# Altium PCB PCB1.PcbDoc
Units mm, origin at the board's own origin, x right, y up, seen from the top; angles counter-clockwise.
Board outline 98 x 98 mm, 2 copper layers (Top Layer, Bottom Layer); 41 components, 34 nets, 175 pads, 20 vias.
Unrouted connection lines stored in the file: 90.
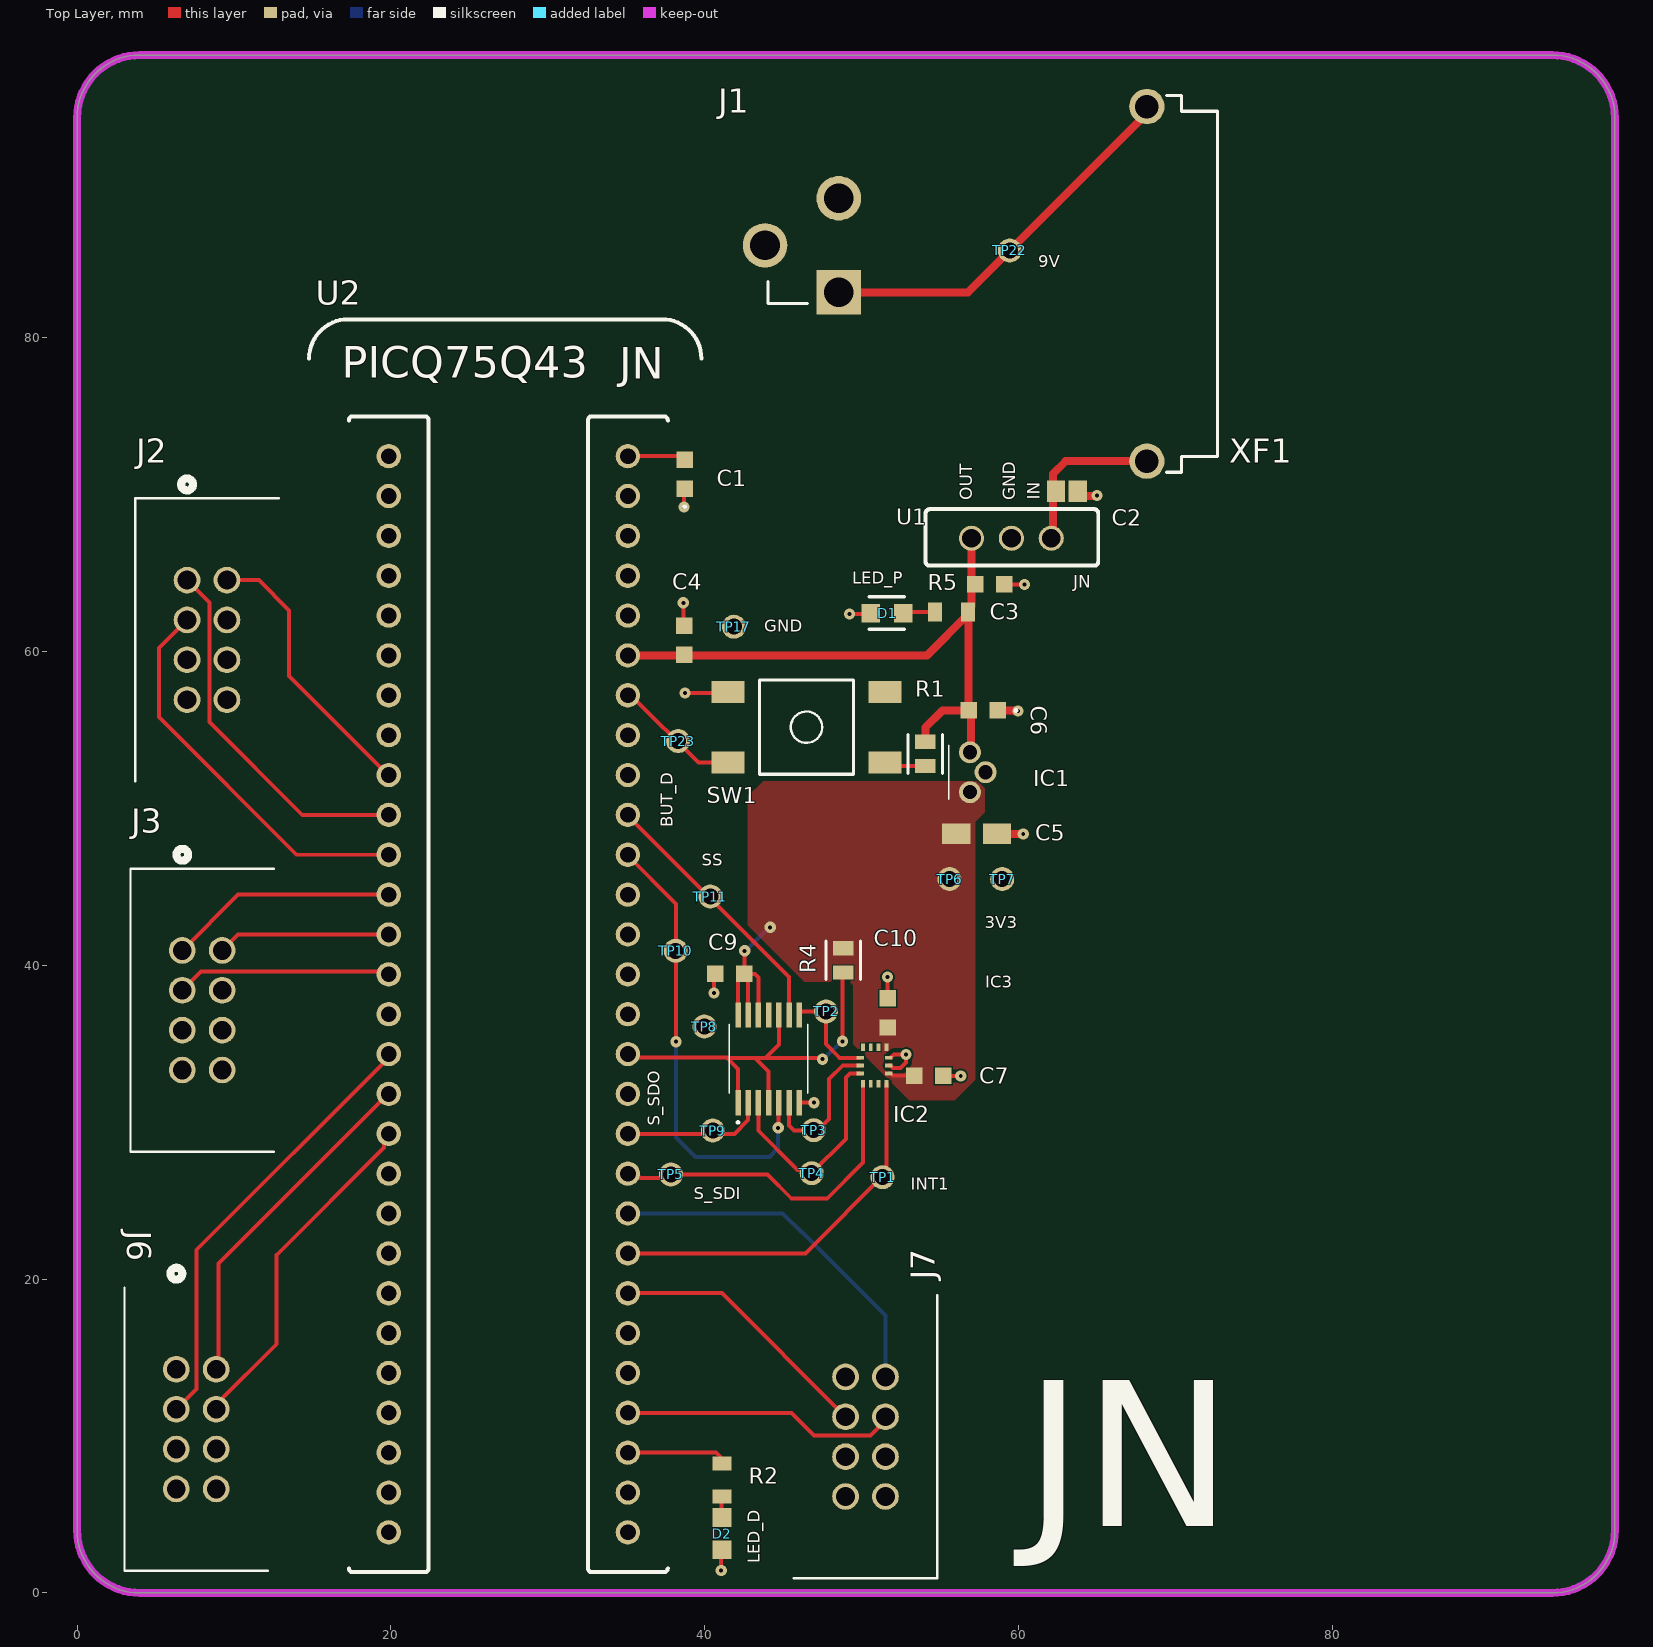
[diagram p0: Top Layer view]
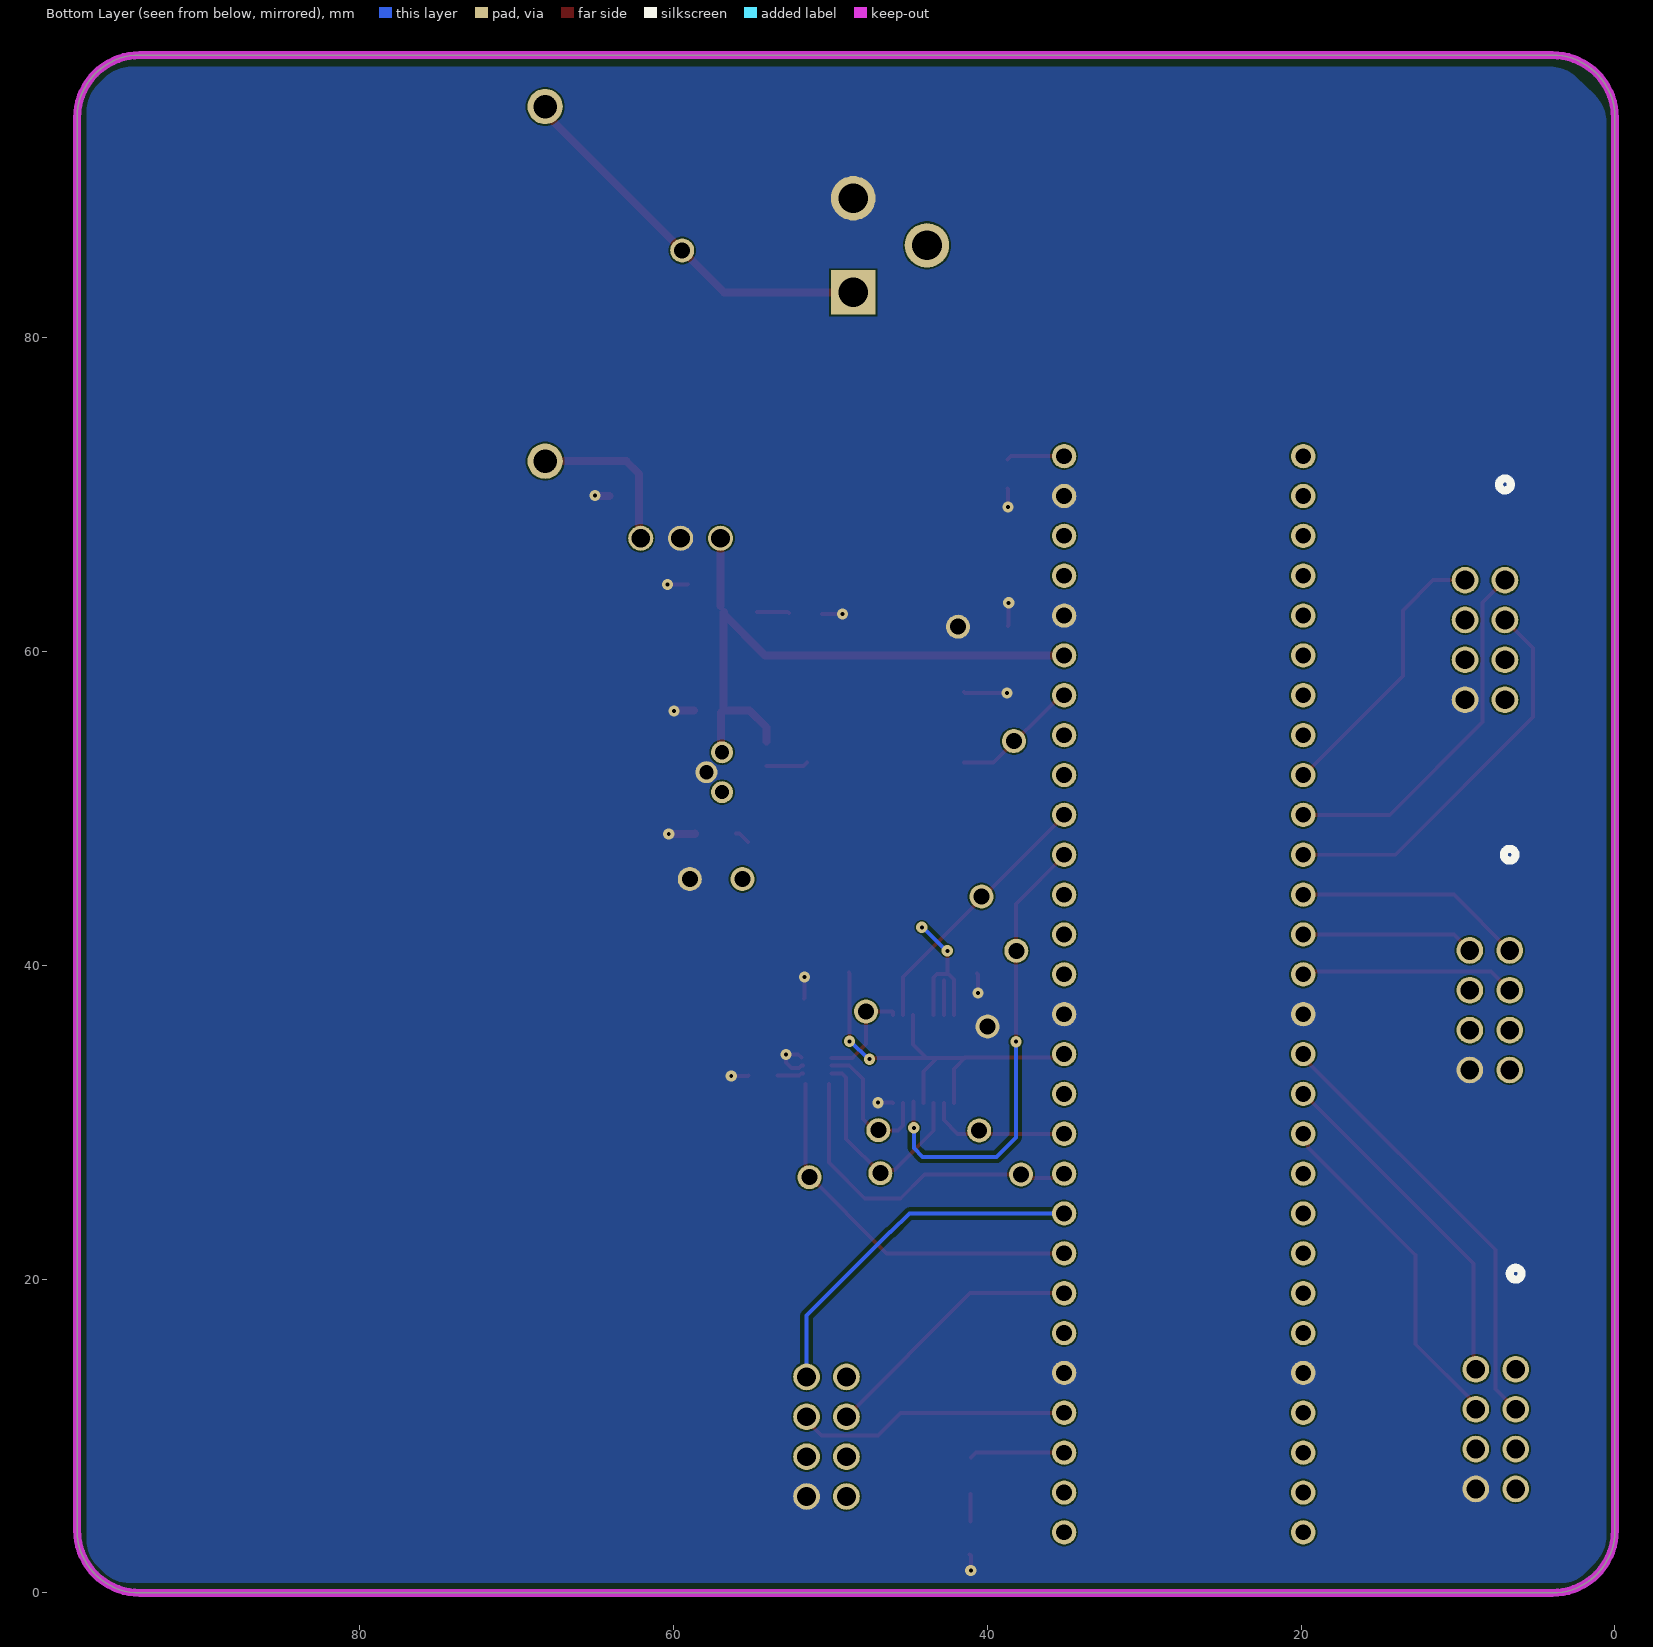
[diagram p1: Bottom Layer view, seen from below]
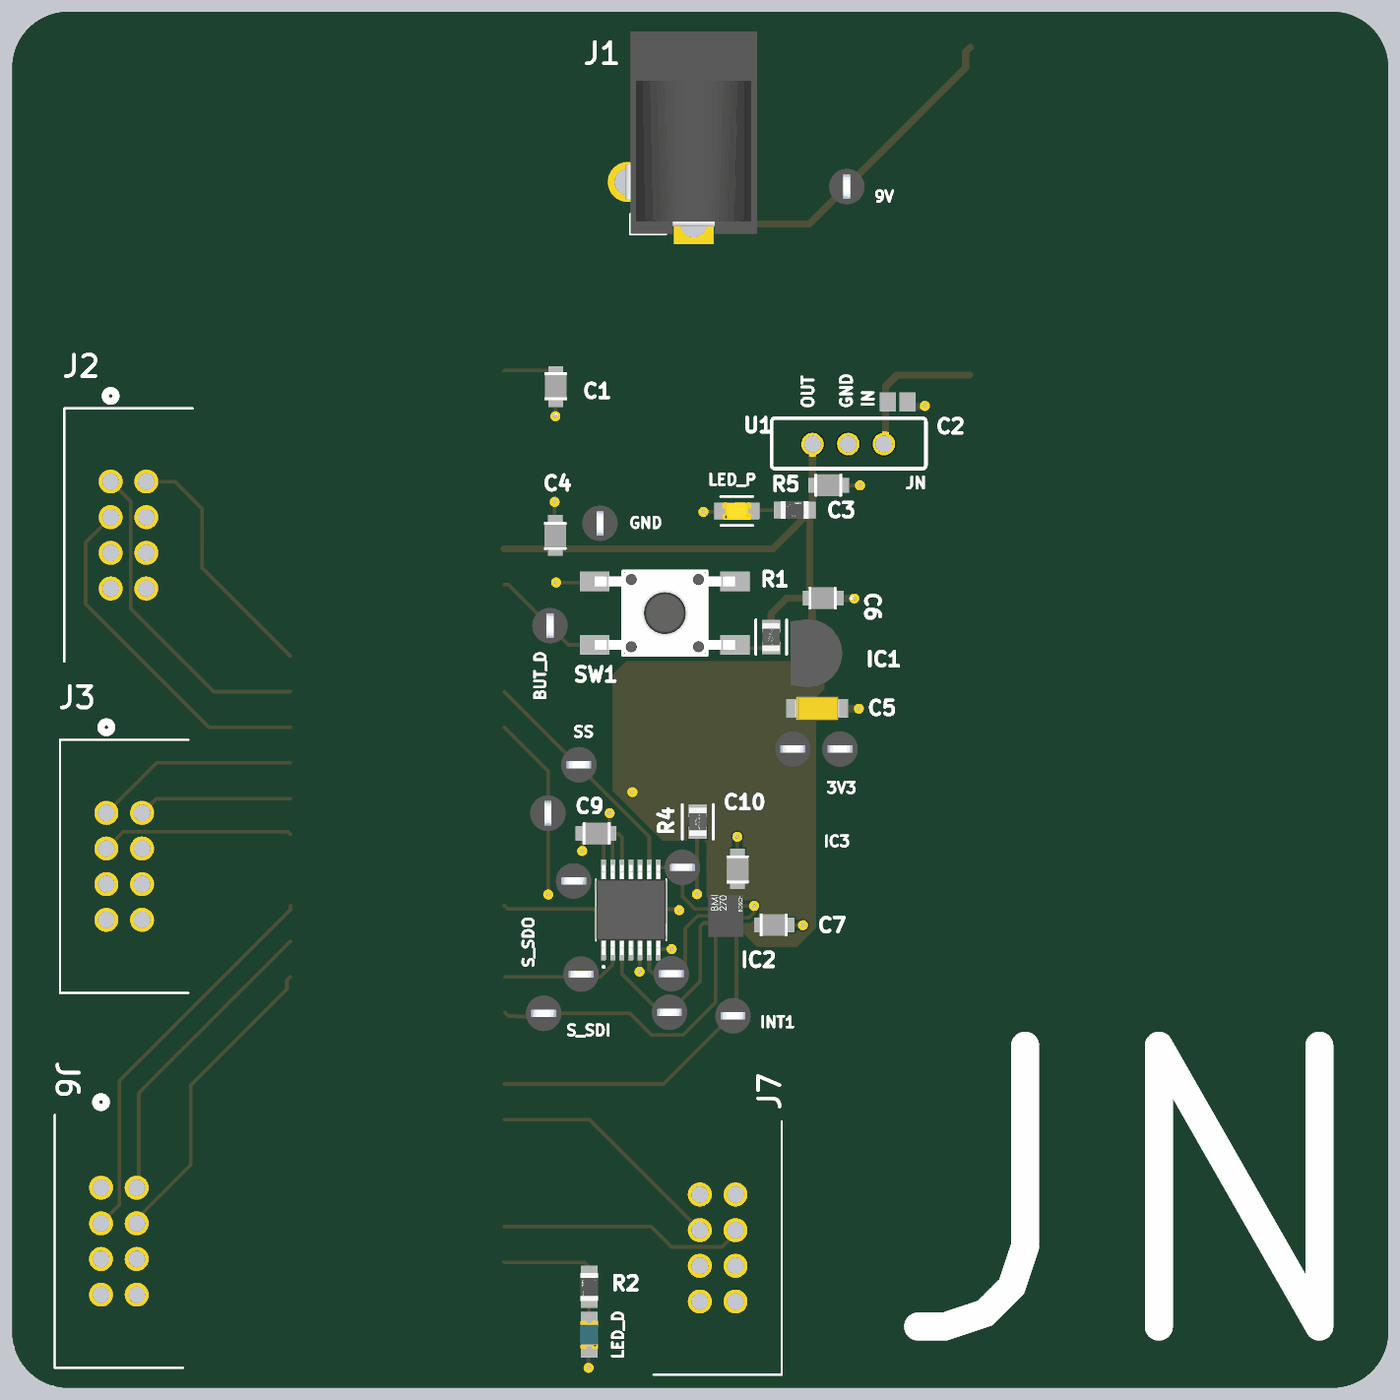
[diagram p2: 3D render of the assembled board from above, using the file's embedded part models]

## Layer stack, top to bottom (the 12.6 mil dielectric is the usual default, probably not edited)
Top Solder: solder mask 0.0102, Solder Resist, Dk 3.5
Top Layer: signal copper 0.0356
Dielectric 1: dielectric 0.32, FR-4, Dk 4.8
Bottom Layer: signal copper 0.0356
Bottom Solder: solder mask 0.0102, Solder Resist, Dk 3.5

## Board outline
0,4 0,94 cw(c4,94) 4,98 94,98 cw(c94,94) 98,94 98,4 cw(c94,4) 94,0 4,0 cw(c4,4)

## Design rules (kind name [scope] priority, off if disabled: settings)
Clearance PTH_Hole_to_Copper [IsPad and (HoleSize > 0) vs IsPad and (HoleSize > 0)] p1: gap=0.102 ignorepadtopadclearanceinfootprint=FALSE except(0.076: SMDPad-Fill SMDPad-Poly SMDPad-Region; 0.3: Fill-Hole Poly-Hole Region-Hole; 0.35: Arc-Hole Track-Hole)
Clearance Via_Hole_to_Copper [IsVia vs IsVia] p2: gap=0.102 ignorepadtopadclearanceinfootprint=FALSE except(0.076: SMDPad-Fill SMDPad-Poly SMDPad-Region; 0.2: Arc-Hole Track-Hole Fill-Hole Poly-Hole Region-Hole)
Clearance Same_Net_Track [IsTrack vs IsTrack] p3: gap=0.102 ignorepadtopadclearanceinfootprint=FALSE except(0.076: SMDPad-Fill SMDPad-Poly SMDPad-Region; 0.25: Arc-Arc Arc-Track Track-Track)
Clearance [All] p4: gap=0.102 ignorepadtopadclearanceinfootprint=FALSE except(0.051: Text-Text; 0.076: SMDPad-Fill SMDPad-Poly SMDPad-Region; 0.15: SMDPad-SMDPad; 0.254: Track-Poly)
ComponentClearance [All] p1: gap=0.254 collisioncheckmode=3 verticalgap=0.508 showdistances=FALSE
HoleSize [All] p1: absolutevalues=TRUE maxlimit=6.3 minlimit=0.15 maxpercent=80.000 minpercent=20.000
HoleToHoleClearance Via_Hole_to_Hole [IsVia vs IsVia] p1: gap=0.2 allowstackedmicrovias=TRUE
HoleToHoleClearance Pad_Hole_to_Hole [IsPad vs IsPad] p2: gap=0.45 allowstackedmicrovias=TRUE
MinimumAnnularRing PTH_Annular_Ring [IsPad and (HoleSize > 0)] p1: minimumring=0.2
MinimumAnnularRing Via_Annular_Ring [IsVia] p2: minimumring=0.075
MinimumSolderMaskSliver [All] p1: minsoldermaskwidth=0.1
PolygonConnect [All] p1: connectstyle=Direct reliefconductorwidth=0.254 reliefentries=4 polygonreliefangle="90 Angle" airgapwidth=0.254
RoutingVias [All] p1: holewidth=0.254 width=0.711 viastyle="Through Hole" minholewidth=0.15 minwidth=0.3 maxholewidth=6.3 maxwidth=6.6
SilkToSolderMaskClearance [IsPad] p1: minsilkscreentomaskgap=0.15 clearancetoexposedcopper=TRUE
SolderMaskExpansion [All] p1: expansion=0 istentingtop=FALSE
SupplyNets "Schematic Supply Nets_8" [InNet('+9V')] p1: voltage=0.000
SupplyNets "Schematic Supply Nets_7" [InNet('+5V_IN')] p2: voltage=0.000
SupplyNets "Schematic Supply Nets_6" [InNet('+5V_BUS')] p3: voltage=0.000
SupplyNets "Schematic Supply Nets_4" [InNet('+3V3')] p4: voltage=0.000
SupplyNets "Schematic Supply Nets_2" [InNet('GND')] p5: voltage=0.000
UnRoutedNet [All] p1: checkbadconnections=TRUE
Width [All] p1: maxlimit=0.508 minlimit=0.1 preferedwidth=0.254
24 further rules are at their usual default settings.

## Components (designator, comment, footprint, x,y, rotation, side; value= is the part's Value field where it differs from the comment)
C1 ".1uF 25V" C2012_Commercial 38.71,71.298 r90 top
C2 ".33uF 35V" CAPC2113X120X50LL20T30 63.068,70.206 r180 top
C3 ".1uF 25V" C2012_Commercial 58.153,64.277 r180 top
C4 ".1uF 25V" C2012_Commercial 38.684,60.706 r270 top
C5 "2.2uF 35V" CAPPM3216X180N 57.323,48.387 r0 top
C6 "1uF 25V" C2012_Commercial 57.76,56.236 r180 top
C7 ".1uF 25V" C2012_Commercial 54.28,32.969 r180 top
C9 ".1uF 25V" C2012_Commercial 41.58,39.472 r0 top
C10 ".1uF 25V" C2012_Commercial 51.664,36.957 r270 top
D1 "LED_Y" FP-SM0805YCL-MFG 51.613,62.433 r180 top
D2 "LED_B" FP-SM0805UBWC-MFG 41.097,3.785 r270 top
IC1 "LP2950-33LPRE3" TL431CLPM 56.896,51.029 r90 top
IC2 "BMI270" BMI270 50.825,33.604 r90 top
IC3 "SN74LVC125APWR" SN74LVC125APWR 44.069,34.036 r0 top
J1 "PJ-102AH" PJ102AH 48.539,82.875 r270 top
J2 "702460801" CONN_7024608xx_MOL 7.01,64.541 r270 top
J3 "702460801" CONN_7024608xx_MOL 6.706,40.945 r270 top
J6 "702460801" CONN_7024608xx_MOL 6.325,14.249 r270 top
J7 "702460801" CONN_7024608xx_MOL 48.971,13.767 r270 top
R1 "10k .125W" FP-CRGCQ0805-IPC_C 54.051,53.467 r90 top value=10KΩ
R2 "562R .125W" FP-RT0805-MFG 41.097,7.188 r90 top value=562Ω
R4 "10k .125W" FP-CRGCQ0805-IPC_C 48.819,40.31 r90 top value=10KΩ
R5 "562R  .125W" FP-RT0805-MFG 55.728,62.509 r0 top value=562Ω
SW1 "Button" FP-1301_9320-MFG 46.482,55.169 r0 top
TP1 "5001" KEYSTONE_5001 51.333,26.492 r0 top
TP2 "5001" KEYSTONE_5001 47.727,37.059 r0 top
TP3 "5001" KEYSTONE_5001 46.939,29.489 r0 top
TP4 "5001" KEYSTONE_5001 46.812,26.746 r0 top
TP5 "5001" KEYSTONE_5001 37.846,26.67 r0 top
TP6 "5001" KEYSTONE_5001 55.601,45.491 r0 top
TP7 "5001" KEYSTONE_5001 58.953,45.491 r0 top
TP8 "5001" KEYSTONE_5001 39.98,36.093 r0 top
TP9 "5001" KEYSTONE_5001 40.513,29.464 r0 top
TP10 "5001" KEYSTONE_5001 38.151,40.919 r90 top
TP11 "5001" KEYSTONE_5001 40.361,44.374 r0 top
TP17 "5001" KEYSTONE_5001 41.859,61.57 r90 top
TP22 "5001" KEYSTONE_5001 59.436,85.547 r90 top
TP23 "5001" KEYSTONE_5001 38.303,54.28 r90 top
U1 "LM7805_JN" LM7805_JN 62.078,67.208 r180 top
U2 "PIC18F57Q43" PIC1857Q43_JN 14.783,-8.839 r0 top
XF1 "1A Fuse" 696101000002 1338.174,-1186.583 r270 top

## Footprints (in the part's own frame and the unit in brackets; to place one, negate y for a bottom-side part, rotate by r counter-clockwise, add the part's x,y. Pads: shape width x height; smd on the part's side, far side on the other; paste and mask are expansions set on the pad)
696101000002 [mm] "FUSEHOLDER BLOCKS - PCB - CLIP COVER - THT"
  round 2.25 hole 1.5: 1(-1281.3,-1270) 2(-1258.7,-1270)
  silkscreen extent -1282,-1268.74 -1258,-1265.5, body extent -1282,-1274.5 -1258,-1265.5, height 13.55
BMI270 [mm]
  rect 0.475x0.25 smd mask+0.05: 1(-1.163,0.75) 2(-1.163,0.25) 3(-1.163,-0.25) 4(-1.163,-0.75) 8(1.162,-0.75) 9(1.162,-0.25) 10(1.162,0.25) 11(1.162,0.75)
  rect 0.25x0.475 smd mask+0.05: 5(-0.5,-0.913) 6(0,-0.913) 7(0.5,-0.913) 12(0.5,0.913) 13(0,0.913) 14(-0.5,0.913)
  body extent -1.5,-1.25 1.5,1.25, height 0.83
C2012_Commercial [mm]
  rect 1.05x1.05 smd: 1(-0.925,0) 2(0.925,0)
  silkscreen extent -2.12,-0.05 -2.03,0.05, body extent -0.96,-0.8 1.04,0.8, height 1.25
CAPC2113X120X50LL20T30 [mm] "Chip Capacitor, 2-Leads, Body 2.05x1.25mm, IPC High Density"
  rect 1.15x1.35 smd: 1(-0.7,0) 2(0.7,0)
  body extent -1.13,-0.72 1.12,0.72, height 1.2
CAPPM3216X180N [mm]
  rect 1.8x1.3 smd: 1(-1.3,0) 2(1.3,0)
  body extent -1.6,-0.82 1.6,0.82, height 1.8
CONN_7024608xx_MOL [mil]
  round 67 / inner round 60 / far side round 67 hole 47 paste-99999 mask+0: 1(0,0) 2(0,100) 3(100,0) 4(100,100) 5(200,0) 6(200,100) 7(300,0) 8(300,100)
  silkscreen extent -255,-130 505,230
FP-1301_9320-MFG [mm]
  rect 2.1x1.4 smd paste+0 mask+0: 1(-5,2.25) 2(5,2.25) 3(-5,-2.25) 4(5,-2.25)
  silkscreen extent -3,-3 3,3, body extent -6.15,-3.1 6.15,3.1, height 0.25
FP-CRGCQ0805-IPC_C [mm]
  rect 0.906x1.31 smd paste+0 mask+0: 1(-0.776,0) 2(0.776,0)
  silkscreen extent -1.23,-1.1 1.23,1.1, body extent -1.33,-0.8 1.33,0.8, height 0.25
FP-RT0805-MFG [mm]
  rect 0.9x1.2 smd paste+0 mask+0: 1(-1.05,0) 2(1.05,0)
  body extent -1.6,-0.77 1.6,0.77, height 0.25
FP-SM0805UBWC-MFG [mil]
  rect 47x47 smd paste+0 mask+0: 1(-40.5,0) 2(40.5,0)
  body extent -68,-33 68,33, height 10
FP-SM0805YCL-MFG [mil]
  rect 47x47 smd paste+0 mask+0: 1(-40.5,0) 2(40.5,0)
  silkscreen extent -44,-41 45,40, body extent -68,-33 68,33, height 10
KEYSTONE_5001 [mm]
  round 1.53 hole 1.02: TP(0,0)
  body extent -1.27,-1.27 1.27,1.27, height 4.57
LM7805_JN [mm]
  round 1.6 hole 1.2 paste-2539.97 mask+0.1: 1(0,0) 2(2.54,0) 3(5.08,0)
  silkscreen extent -3,-1.85 8,1.75
PIC1857Q43_JN [mm]
  round 1.55 hole 1 paste-2539.97 mask+0.1: 1(5.08,81.28) 2(5.08,78.74) 3(5.08,76.2) 4(5.08,73.66) 5(5.08,71.12) 6(5.08,68.58) 7(5.08,66.04) 8(5.08,63.5) 9(5.08,60.96) 10(5.08,58.42) 11(5.08,55.88) 12(5.08,53.34) 13(5.08,50.8) 14(5.08,48.26) 15(5.08,45.72) 16(5.08,43.18) 17(5.08,40.64) 18(5.08,38.1) 19(5.08,35.56) 20(5.08,33.02) 21(5.08,30.48) 22(5.08,27.94) 23(5.08,25.4) 24(5.08,22.86) 25(5.08,20.32) 26(5.08,17.78) 27(5.08,15.24) 28(5.08,12.7) 29(20.32,81.28) 30(20.32,78.74) 31(20.32,76.2) 32(20.32,73.66) 33(20.32,71.12) 34(20.32,68.58) 35(20.32,66.04) 36(20.32,63.5) 37(20.32,60.96) 38(20.32,58.42) 39(20.32,55.88) 40(20.32,53.34) 41(20.32,50.8) 42(20.32,48.26) 43(20.32,45.72) 44(20.32,43.18) 45(20.32,40.64) 46(20.32,38.1) 47(20.32,35.56) 48(20.32,33.02) 49(20.32,30.48) 50(20.32,27.94) 51(20.32,25.4) 52(20.32,22.86) 53(20.32,20.32) 54(20.32,17.78) 55(20.32,15.24) 56(20.32,12.7)
  silkscreen extent 0,10.16 25,90
PJ102AH [mm]
  rect 2.835x2.835 hole 1.89: 1(0,0)
  round 2.835 hole 1.89: 2(-6,0) 3(-3,-4.7)
  silkscreen extent -0.7,-4.5 0.7,-2, body extent -13.7,-4.9 0.7,4.5, height 11.5
SN74LVC125APWR [mm]
  rect 0.35x1.6 smd: 1(-1.95,-2.8) 2(-1.3,-2.8) 3(-0.65,-2.8) 4(0,-2.8) 5(0.65,-2.8) 6(1.3,-2.8) 7(1.95,-2.8) 8(1.95,2.8) 9(1.3,2.8) 10(0.65,2.8) 11(0,2.8) 12(-0.65,2.8) 13(-1.3,2.8) 14(-1.95,2.8)
  silkscreen extent -2.5,-4.1 2.5,2.2, body extent -2.5,-3.2 2.5,3.2, height 1.13
TL431CLPM [mm]
  round 1.4 hole 0.9: 1(0,0) 2(1.27,-1) 3(2.54,0)
  silkscreen extent -0.45,1.35 2.99,1.35, body extent -1.13,-2.22 3.69,1.46, height 4.91

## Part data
C1 C3 C4 C7 C9 C10: library part C2012X7R1V105K085AB, "Capacitor / C0805C104J3RACTU / 0805", Manufacturer_Name=TDK, Mouser Part Number=810-C2012X7R1V105K0B
C2: library part CMP-2007-04070-1, "TAJR334K035RNJ", Manufacturer="AVX Interconnect / Elco"
C5: library part TPSA225K035R1500, "Capacitor Polarised / 1.5ohm ESR for Output Requirement / Tantalum / 1206", Manufacturer_Name="Kyocera AVX", Mouser Part Number=581-TPSA225K035R1500
C6: library part C2012X7R1V105K085AB, "Capacitor / C0805C105K3RACTU / 0805", Manufacturer_Name=TDK, Mouser Part Number=810-C2012X7R1V105K0B
D1: library part CMP-35283-000007-1, "LED YELLOW CLEAR 0805 SMD /  / SM0805YCL", Case Code (Imperial)=0805, Case Code (Metric)=2012, Color=Yellow, Forward Current=2mA, Forward Voltage=1.9V, Lens Color=Colorless, Max Operating Temperature=80°C, Min Operating Temperature=-30°C, Package Quantity=4000
D2: library part CMP-35283-000004-1, "LED BLUE CLEAR 0805 SMD /  / SM0805UBWC", Case Code (Imperial)=0805, Case Code (Metric)=2012, Color=Blue, Forward Current=20mA, Forward Voltage=3.3V, Lens Color=Colorless, Max Operating Temperature=80°C, Min Operating Temperature=-30°C, Package Quantity=3000, Power Rating=100mW
IC1: "Integrated Circuit", Manufacturer_Name="Texas Instruments", Mouser Part Number=595-LP2950-33LPRE3
IC2: "IMU"
IC3: "Integrated Circuit", Manufacturer_Name="Texas Instruments", Mouser Part Number=595-SN74LVC125APWR
J1: "Connector", Manufacturer_Name="Same Sky", Mouser Part Number=490-PJ-102AH
J2 J3 J6 J7: "2.54mm Pitch C-Grid Header, Low Profile, Dual Row, Vertical, Shrouded, 8  Circuits, 0.38Âµm Gold (Au) Selective Plating", Manufacturer_Name="Molex Connector Corporation"
R1 R4: library part CMP-03211-002989-1, "CRGCQ0805J10K", Ambient Temperature Range High=+70°C, Manufacturer="TE Connectivity", Package=CRGCQ0805, Power Rating=0.125W, Resistance=10KΩ, Temperature="-55°C to +155°C", Temperature Coefficient=±100ppm/°C, Temperature Range High=+155°C, Temperature Range Low=-55°C, Tolerance=0.05, Voltage Rating=150V
R2 R5: library part CMP-03412-035770-1, "RES SMD 562 OHM 1% 1/8W 0805 / RC0805FR-07562RL", Manufacturer=Yageo, Manufacturer Part Number=RT0805FRD07562RL, Package=RT0805, Power Rating=0.125W, Resistance=562Ω, Temperature="-55°C to +155°C", Temperature Coefficient="25 ppm/°C", Temperature Range High=+155°C, Temperature Range Low=-55°C, Tolerance=0.0001, Voltage Rating=150V
SW1: library part CMP-26321-000001-1, "SWITCH TACTILE SPST-NO 0.05A 12V / 1301.9320", Contact Current Rating=50mA, Contact Resistance=100mΩ, Manufacturer=Schurter, Manufacturer Part Number=1301.9320, Operating Force=1.6N, Package=0, Temperature="-20°C to +70°C", Temperature Range High=+70°C, Temperature Range Low=-20°C, Voltage Rating Dc=12V
TP1 TP2 TP3 TP4 TP5 TP6 TP7 TP8 TP9 TP10 TP11 TP17 TP22 TP23: library part CMP-003-000000-1, Package=None
U1: library part LM7805_JN_1
U2: library part PIC18F57Q43_JN
XF1: library part CMP-1502-00233-4, "WR-FSH Fuse Holder Blocks Fuse Holder Blocks Clip Cover for PCB /  / 696101000002", Fuse Current=10A, Max Operating Temperature=120°C, Min Operating Temperature=-30°C, Voltage Rating (AC)=250V

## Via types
v1: diameter 0.711, hole 0.254, Top Layer to Bottom Layer, 20 vias

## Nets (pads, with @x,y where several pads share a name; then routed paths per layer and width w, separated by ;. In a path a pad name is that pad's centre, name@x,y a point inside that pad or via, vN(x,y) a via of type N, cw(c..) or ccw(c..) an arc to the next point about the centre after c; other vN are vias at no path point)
+3V3: C5.1 C7.2 C9.2 C10.2 IC1.1 IC2.5 IC2.8 IC3.12 IC3.13 IC3.14 R4.2 TP6.TP | length 14.8
  Top Layer w0.254: IC3.14 42.119,39.086 42.545,39.512 v1(42.545,40.919) ; C9.2 42.53,39.446 43.205,39.446 43.419,39.233 IC3.12 ; IC3.13 C9.2@42.769,39.04 ; IC2.5 51.847,33.104 51.982,32.969 C7.2 ; C5.1@55.25,47.864 55.773,48.387 C5.1
  Bottom Layer w0.254: v1(42.545,40.919) 42.608,40.919 44.107,42.418 v1(44.171,42.418)
+5V_BUS: C1.2 U2.29 | length 3.7
  Top Layer w0.254: U2.29@35.052,72.441 38.492,72.441 C1.2
+5V_IN: C3.2 C4.2 C6.2 IC1.3 R1.2 R5.2 U1.3 U2.34 | length 40.3
  Top Layer w0.508: U2.34@35.052,59.741 54.159,59.741 56.778,62.359 R5.2 56.806,62.481 56.806,56.264 56.962,56.108 56.962,53.899 IC1.3@57.09,53.772 ; R1.2 54.051,55.143 55.143,56.236 C6.2 ; R5.2@56.998,62.879 U1.3
+9V: J1.1 TP22.TP XF1.1 | length 25.5
  Top Layer w0.508: J1.1 56.763,82.875 TP22.TP 67.891,94.002 67.891,95.12 XF1.1@68.224,95.453
BUT_D: SW1.3 TP23.TP U2.35 | length 8.2
  Top Layer w0.254: U2.35@35.052,57.201 35.306,57.201 39.599,52.908 41.471,52.908 SW1.3
GND: C1.1 C2.1 C3.1 C4.1 C5.2 C6.1 C7.1 C9.1 C10.1 D1.2 D2.2 IC1.2 IC2.6 IC2.7 IC3.7 J1.2 J2.8 J3.8 J6.8 J7.8 SW1.1 TP7.TP TP8.TP TP17.TP U1.2 U2.15 U2.24 U2.30 U2.33 U2.43 U2.52 | length 20.6
  Top Layer w0.254: v1(38.633,63.094) 38.633,61.682 C4.1 ; v1(38.684,69.19) 38.684,70.347 C1.1 ; v1(38.735,57.353) 41.416,57.353 SW1.1 ; v1(40.589,38.227) 40.589,39.406 C9.1 ; v1(41.046,1.422) 41.046,2.389 D2.2@41.123,2.465 ; IC3.7 46.025,31.242 v1(46.965,31.242) ; v1(49.225,62.382) D1.2@50.533,62.382 ; v1(51.638,39.243) 51.638,37.907 C10.1 ; IC2.6 51.74,33.602 51.849,33.602 51.989,33.462 51.989,33.458 52.47,33.458 52.814,33.802 52.814,34.297 v1(52.832,34.315) 52.058,34.315 IC2.7@51.849,34.106 ; C7.1 55.23,32.944 v1(56.312,32.944) ; C3.1 59.094,64.262 v1(60.376,64.262)
  Top Layer w0.508: C5.2 58.636,48.374 60.282,48.374 v1(60.295,48.362) ; C6.1 58.697,56.223 59.957,56.223 v1(59.969,56.21) ; C2.1@64.073,69.901 v1@64.999,69.901
  other v1: 64.999,69.926
GPIO1: J7.2 U2.48 | length 23.1
  Bottom Layer w0.254: U2.48@35.052,24.181 44.958,24.181 46.152,22.987 46.19,22.987 51.511,17.666 J7.2
GPIO2: J7.3 U2.50 | length 17.2
  Top Layer w0.254: U2.50@35.052,19.101 41.097,19.101 J7.3
GPIO3: J7.4 U2.53 | length 17.7
  Top Layer w0.254: U2.53@35.052,11.481 45.517,11.481 46.965,10.033 50.571,10.033 51.511,10.973 J7.4
GPIO4: J6.2 U2.17 | length 22.1
  Top Layer w0.254: J6.2 9.017,14.402 9.017,21.006 U2.17@19.812,31.801
GPIO5: J6.3 U2.16 | length 28.2
  Top Layer w0.254: J6.3 7.62,13.005 7.62,21.869 19.812,34.061 U2.16@19.812,34.341
GPIO6: J6.4 U2.18 | length 22.1
  Top Layer w0.254: J6.4 8.865,12.014 12.725,15.875 12.725,21.539 19.567,28.381 19.567,29.016 U2.18@19.812,29.261
IMU_CLK: IC2.13 IC3.6 TP3.TP | length 9.9
  Top Layer w0.254: IC3.6 45.369,29.79 45.695,29.464 46.838,29.464 47.219,29.083 47.219,29.489 47.93,30.201 47.93,32.741 48.793,33.604 IC2.13
IMU_SDI: IC2.14 IC3.3 TP4.TP | length 14.3
  Top Layer w0.254: IC3.3 43.419,29.454 45.914,26.959 46.6,26.959 TP4.TP 48.997,28.931 48.997,32.855 49.246,33.104 IC2.14
IMU_SS: IC2.12 IC3.8 TP2.TP | length 6.5
  Top Layer w0.254: IC3.8 46.019,37.011 46.067,37.059 TP2.TP 47.727,34.976 48.598,34.104 IC2.12
INT1: IC2.4 TP1.TP U2.49 | length 24.3
  Top Layer w0.254: U2.49@35.052,21.641 42.875,21.641 46.406,21.641 51.575,26.81 IC2.4
LED_D: R2.2 U2.54 | length 6.1
  Top Layer w0.254: U2.54@35.052,8.941 40.725,8.941 R2.2@41.046,8.619
LLS_EN: IC3.1 IC3.4 IC3.10 R4.1 U2.44 | length 28.1
  Top Layer w0.254: U2.44@35.052,34.341 35.281,34.112 41.402,34.112 42.119,33.395 IC3.1 ; 41.427,34.087 43.205,34.087 ; 43.909,34.13 44.719,34.94 IC3.10 ; IC3.4 44.069,33.223 43.205,34.087 ; v1(47.498,34.011) 47.422,34.087 43.205,34.087 ; v1(48.768,35.154) 48.768,39.483 R4.1
  Bottom Layer w0.254: v1(47.498,34.011) 47.561,34.011 48.704,35.154 v1(48.768,35.154)
NetC2_2: C2.2 U1.1 XF1.2 | length 10.5
  Top Layer w0.508: U1.1 62.198,67.328 62.198,71.316 62.998,72.117 XF1.2
NetD1_1: D1.1 R5.1 | length 2.1
  Top Layer w0.254: D1.1 52.718,62.509 R5.1
NetD2_1: D2.1 R2.1 | length 1.7
  Top Layer w0.254: D2.1@41.072,4.567 R2.1@41.072,6.299
NetR1_1: R1.1 SW1.4 | length 2.7
  Top Layer w0.254: SW1.4 51.71,52.691 R1.1
RB1: J2.3 U2.11 | length 25.1
  Top Layer w0.254: J2.3 5.232,60.223 5.232,55.804 13.995,47.041 U2.11@19.812,47.041
RB2: J2.2 U2.9 | length 17.9
  Top Layer w0.254: J2.2 11.582,64.541 13.513,62.611 13.513,58.42 U2.9@19.812,52.121
RC4: J2.1 U2.10 | length 23.5
  Top Layer w0.254: J2.1 8.433,63.119 8.433,55.499 14.351,49.581 U2.10@19.812,49.581
RC5: J3.1 U2.12 | length 14.6
  Top Layer w0.254: J3.1 10.262,44.501 U2.12@19.812,44.501
RC6: J3.2 U2.13 | length 11
  Top Layer w0.254: J3.2 10.262,41.961 U2.13@19.812,41.961
RD4: J3.3 U2.14 | length 13.7
  Top Layer w0.254: J3.3 7.899,39.599 19.634,39.599 U2.14@19.812,39.421
RX: U2.26
SPI2_CLK: IC3.5 TP10.TP U2.39 | length 29.5
  Top Layer w0.254: U2.39@35.052,47.041 38.176,43.917 v1(38.176,35.128) ; v1(44.679,29.642) 44.699,29.662 44.699,31.317 IC3.5@44.704,31.322
  Bottom Layer w0.254: v1(38.176,35.128) 38.176,29.032 39.421,27.788 44.12,27.788 44.679,28.346 v1(44.679,29.642)
SPI2_SDI: IC2.1 TP5.TP U2.47 | length 21.8
  Top Layer w0.254: U2.47 35.351,26.473 35.867,26.473 35.898,26.441 37.617,26.441 TP5.TP 43.993,26.67 45.542,25.121 47.777,25.121 50.075,27.419 IC2.1
SPI2_SDO: IC3.2 TP9.TP U2.46 | length 9.1
  Top Layer w0.254: U2.46 41.885,29.261 42.769,30.145 IC3.2
SPI2_SS: IC3.9 TP11.TP U2.38 | length 17
  Top Layer w0.254: U2.38@35.052,49.581 45.369,39.264 IC3.9
TX: U2.25
pads on no net: IC2.2 IC2.3 IC2.9 IC2.10 IC2.11 IC3.11 J1.3 J2.4 J2.5 J2.6 J2.7 J3.4 J3.5 J3.6 J3.7 J6.1 J6.5 J6.6 J6.7 J7.1 J7.5 J7.6 J7.7 SW1.2 U2.1 U2.2 U2.3 U2.4 U2.5 U2.6 U2.7 U2.8 U2.19 U2.20 U2.21 U2.22 U2.23 U2.27 U2.28 U2.31 U2.32 U2.36 U2.37 U2.40 U2.41 U2.42 U2.45 U2.51 U2.55 U2.56

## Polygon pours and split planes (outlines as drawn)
+3V3 on Top Layer "+3V3_L01_P001" (solid, pour order 1): 46.352,38.941 49.248,38.941 49.455,38.733 49.452,34.977 53.035,31.394 55.931,31.394 57.252,32.715 57.252,49.149 57.836,49.733 57.836,51.283 57.379,51.74 43.713,51.74 42.748,50.775 42.748,42.545
GND on Bottom Layer "GND_L02_P004" (solid, pour order 4): 1.912,96.069 2.428,96.559 cw(c4.176,94.717) 4.176,97.257 94.477,97.257 cw(c94.477,94.717) 96.273,96.513 96.64,96.146 cw(c94.844,94.351) 97.384,94.35 97.384,3.383 cw(c95.043,3.383) 96.698,1.727 96.306,1.335 cw(c94.615,3.026) 94.615,0.635 3.284,0.635 cw(c3.284,2.369) 2.057,1.143 1.303,1.898 cw(c3.099,3.694) 0.559,3.694 0.559,93.664 cw(c3.099,93.664) 1.303,95.461

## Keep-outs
Keep-Out Layer:
  the board outline again, w0.508

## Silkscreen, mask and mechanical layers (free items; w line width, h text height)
Top Overlay:
  text "9V" at 61.239,84.48 h0.76
  text "LED_P" at 49.403,64.313 h0.76
  text "GND" at 43.79,61.239 h0.76
  text "BUT_D" at 37.973,48.793 h0.76 r90
  text "SS" at 39.802,46.355 h0.76
  text "3V3" at 57.836,42.367 h0.76
  text "S_SDO" at 37.135,29.769 h0.76 r90
  text "INT1" at 53.111,25.679 h0.76
  text "S_SDI" at 39.294,25.095 h0.76
  text "JN" at 60.344,4.261 h20
  text "LED_D" at 43.51,1.905 h0.76 r90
